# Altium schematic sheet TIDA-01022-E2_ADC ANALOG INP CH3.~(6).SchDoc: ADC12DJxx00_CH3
size 431 x 279 mm; Date: Not shown in title block; ApprovedBy: Not shown in title block; CheckedBy: Not shown in title block; Author: Not shown in title block; CompanyName: Not shown in title block; DrawnBy: Avinash N; Engineer: Not shown in title block; Organization: Not shown in title block; Address1: Not shown in title block; Address2: Not shown in title block; Address3: Not shown in title block; Address4: Not shown in title block; DocumentNumber: 1; Revision: Use project parameter SCH_Rev; SheetNumber: 4; SheetTotal: 26; PageSetup: Record=PageOptions¦CenterHorizontal=True¦CenterVertical=True¦PrintScale=1.00¦XCorrection=1.00¦YCorrection=1.00¦PrintKind=0¦BorderSize=5000000¦LeftOffset=0¦BottomOffset=0¦Orientation=2¦PaperLength=1000¦PaperWidth=1000¦Scale=100¦PaperSource=15¦PrintQuality=600¦MediaType=1¦DitherType=10¦PaperKind=Letter¦PrintScaleMode=1
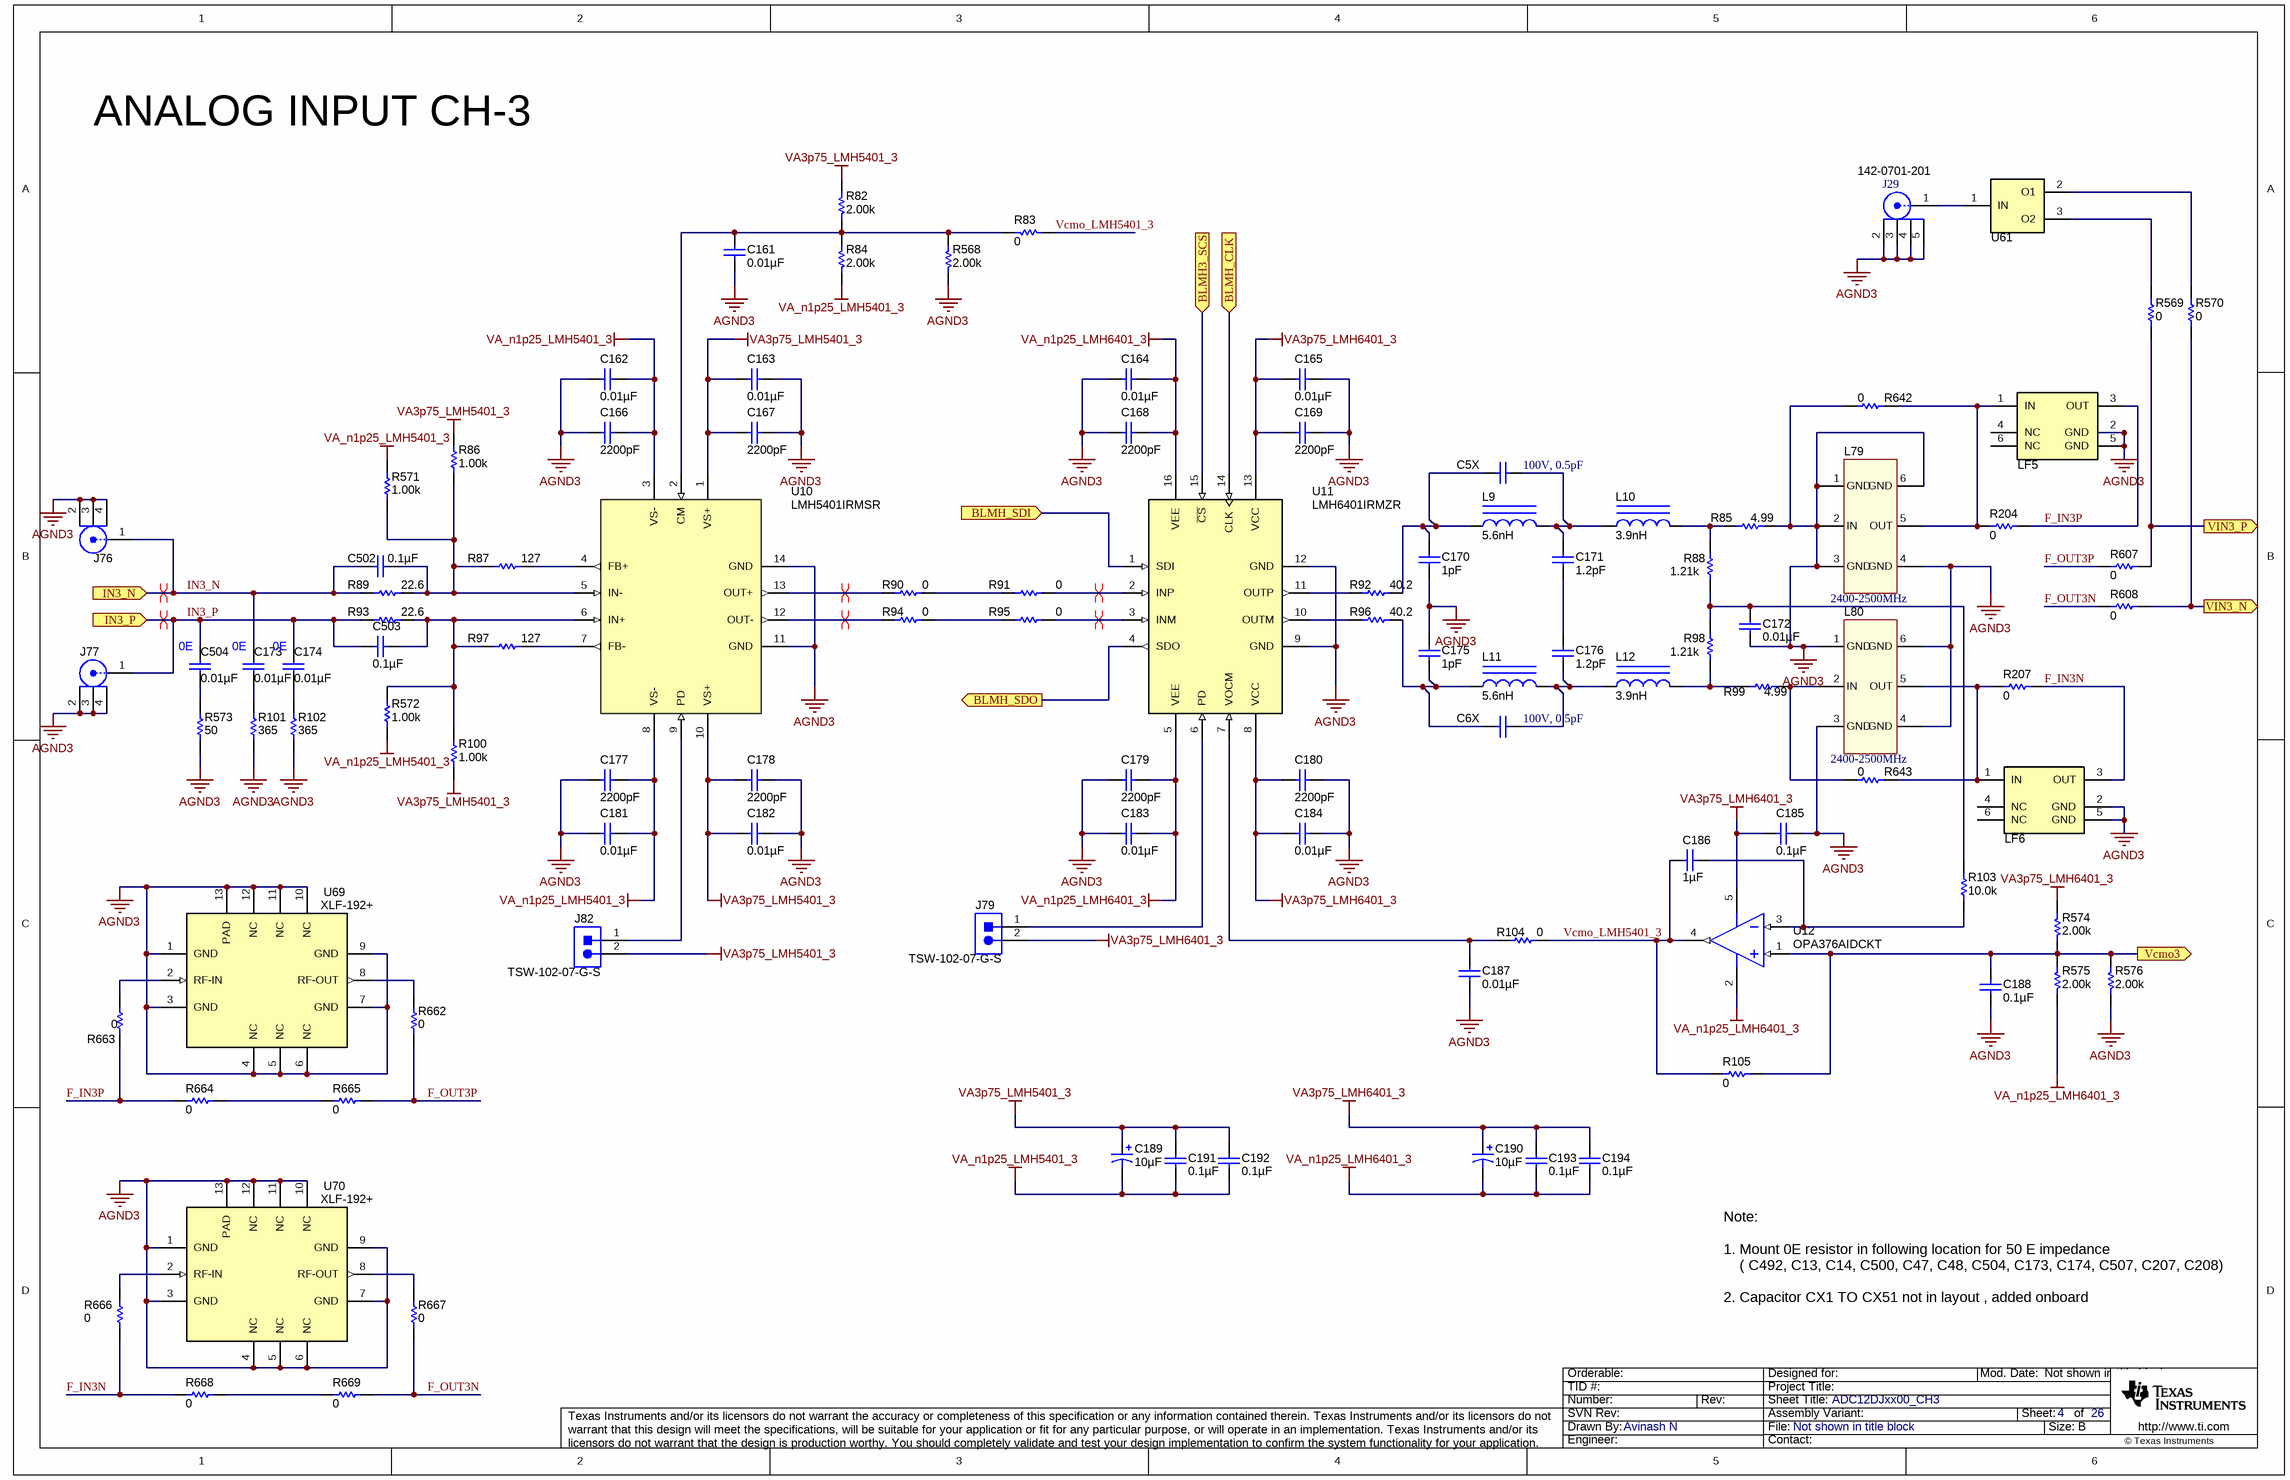
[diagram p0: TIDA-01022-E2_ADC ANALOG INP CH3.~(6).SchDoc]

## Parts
C5X  100V, 0.5pF  [0603_1.6x0.8x0.8mm_Reflow Soldering]
C6X  100V, 0.5pF  [0603_1.6x0.8x0.8mm_Reflow Soldering]
C161  ValueDisplayed: 0.01µF  [0402]  (hidden comment: GRM155R71E103KA01D)
C162  ValueDisplayed: 0.01µF  [0306]  (hidden comment: LLL185R71E103MA01L)
C163  ValueDisplayed: 0.01µF  [0306]  (hidden comment: LLL185R71E103MA01L)
C164  ValueDisplayed: 0.01µF  [0306]  (hidden comment: LLL185R71E103MA01L)
C165  ValueDisplayed: 0.01µF  [0306]  (hidden comment: LLL185R71E103MA01L)
C166  ValueDisplayed: 2200pF  [0306]  (hidden comment: LLL185R71H222MA01L)
C167  ValueDisplayed: 2200pF  [0306]  (hidden comment: LLL185R71H222MA01L)
C168  ValueDisplayed: 2200pF  [0306]  (hidden comment: LLL185R71H222MA01L)
C169  ValueDisplayed: 2200pF  [0306]  (hidden comment: LLL185R71H222MA01L)
C170  ValueDisplayed: 1pF  [0402]  (hidden comment: GRM1555C1H1R0CA01D)
C171  ValueDisplayed: 1.2pF  [0402]  (hidden comment: GRM1555C1H1R2BA01D)
C172  ValueDisplayed: 0.01µF  [0402]  (hidden comment: GRM155R71E103KA01D)
C173  ValueDisplayed: 0.01µF  [0402]  (hidden comment: GRM155R71E103KA01D)
C174  ValueDisplayed: 0.01µF  [0402]  (hidden comment: GRM155R71E103KA01D)
C175  ValueDisplayed: 1pF  [0402]  (hidden comment: GRM1555C1H1R0CA01D)
C176  ValueDisplayed: 1.2pF  [0402]  (hidden comment: GRM1555C1H1R2BA01D)
C177  ValueDisplayed: 2200pF  [0306]  (hidden comment: LLL185R71H222MA01L)
C178  ValueDisplayed: 2200pF  [0306]  (hidden comment: LLL185R71H222MA01L)
C179  ValueDisplayed: 2200pF  [0306]  (hidden comment: LLL185R71H222MA01L)
C180  ValueDisplayed: 2200pF  [0306]  (hidden comment: LLL185R71H222MA01L)
C181  ValueDisplayed: 0.01µF  [0306]  (hidden comment: LLL185R71E103MA01L)
C182  ValueDisplayed: 0.01µF  [0306]  (hidden comment: LLL185R71E103MA01L)
C183  ValueDisplayed: 0.01µF  [0306]  (hidden comment: LLL185R71E103MA01L)
C184  ValueDisplayed: 0.01µF  [0306]  (hidden comment: LLL185R71E103MA01L)
C185  ValueDisplayed: 0.1µF  [0402]  (hidden comment: C1005X5R1A104K050BA)
C186  ValueDisplayed: 1µF  [0603]  (hidden comment: C1608X5R1A105K080AC)
C187  ValueDisplayed: 0.01µF  [0402]  (hidden comment: GRM155R71E103KA01D)
C188  ValueDisplayed: 0.1µF  [0402]  (hidden comment: C1005X5R1A104K050BA)
C189  ValueDisplayed: 10µF  [3216-18]  (hidden comment: TPSA106K010R0900)
C190  ValueDisplayed: 10µF  [3216-18]  (hidden comment: TPSA106K010R0900)
C191  ValueDisplayed: 0.1µF  [0402]  (hidden comment: C1005X5R1A104K050BA)
C192  ValueDisplayed: 0.1µF  [0402]  (hidden comment: C1005X5R1A104K050BA)
C193  ValueDisplayed: 0.1µF  [0402]  (hidden comment: C1005X5R1A104K050BA)
C194  ValueDisplayed: 0.1µF  [0402]  (hidden comment: C1005X5R1A104K050BA)
C502  ValueDisplayed: 0.1µF  [0402]  (hidden comment: GRM155R71C104JA88D)
C503  ValueDisplayed: 0.1µF  [0402]  (hidden comment: GRM155R71C104JA88D)
C504  ValueDisplayed: 0.01µF  [0402]  (hidden comment: GRM155R71E103KA01D)
J29  142-0701-201  [Johnson_142-0701-20x]
J76  142-0771-831  [Johnson_142-0771-831]  (value not drawn)
J77  142-0771-831  [Johnson_142-0771-831]  (value not drawn)
J79  TSW-102-07-G-S  [TSW-102-07-G-S]
J82  TSW-102-07-G-S  [TSW-102-07-G-S]
L9  ValueDisplayed: 5.6nH  [LQW18A]  (hidden comment: LQW18AN5N6D10D)
L10  ValueDisplayed: 3.9nH  [0603HC]  (hidden comment: 0603HC-3N9XJLU)
L11  ValueDisplayed: 5.6nH  [LQW18A]  (hidden comment: LQW18AN5N6D10D)
L12  ValueDisplayed: 3.9nH  [0603HC]  (hidden comment: 0603HC-3N9XJLU)
L79  value 2400-2500MHz  [WE-LPF_0603]  (hidden comment: WE-LPF, 748112024)
L80  value 2400-2500MHz  [WE-LPF_0603]  (hidden comment: WE-LPF, 748112024)
LF5  LFL182G45TC3B746  [FIL_LFL18_TC1]  (value not drawn)
LF6  LFL182G45TC3B746  [FIL_LFL18_TC1]  (value not drawn)
R82  ValueDisplayed: 2.00k  [0402]  (hidden comment: CRCW04022K00FKED)
R83  ValueDisplayed: 0  [0402]  (hidden comment: CRCW04020000Z0ED)
R84  ValueDisplayed: 2.00k  [0402]  (hidden comment: CRCW04022K00FKED)
R85  ValueDisplayed: 4.99  [0402]  (hidden comment: CRCW04024R99FKED)
R86  ValueDisplayed: 1.00k  [0402]  (hidden comment: ERJ-2RKF1001X)
R87  ValueDisplayed: 127  [0402]  (hidden comment: CRCW0402127RFKED)
R88  ValueDisplayed: 1.21k  [0402]  (hidden comment: CRCW04021K21FKED)
R89  ValueDisplayed: 22.6  [0402]  (hidden comment: CRCW040222R6FKED)
R90  ValueDisplayed: 0  [0402]  (hidden comment: CRCW04020000Z0ED)
R91  ValueDisplayed: 0  [0402]  (hidden comment: CRCW04020000Z0ED)
R92  ValueDisplayed: 40.2  [0402]  (hidden comment: CRCW040240R2FKED)
R93  ValueDisplayed: 22.6  [0402]  (hidden comment: CRCW040222R6FKED)
R94  ValueDisplayed: 0  [0402]  (hidden comment: CRCW04020000Z0ED)
R95  ValueDisplayed: 0  [0402]  (hidden comment: CRCW04020000Z0ED)
R96  ValueDisplayed: 40.2  [0402]  (hidden comment: CRCW040240R2FKED)
R97  ValueDisplayed: 127  [0402]  (hidden comment: CRCW0402127RFKED)
R98  ValueDisplayed: 1.21k  [0402]  (hidden comment: CRCW04021K21FKED)
R99  ValueDisplayed: 4.99  [0402]  (hidden comment: CRCW04024R99FKED)
R100  ValueDisplayed: 1.00k  [0402]  (hidden comment: ERJ-2RKF1001X)
R101  ValueDisplayed: 365  [0402]  (hidden comment: CRCW0402365RFKED)
R102  ValueDisplayed: 365  [0402]  (hidden comment: CRCW0402365RFKED)
R103  ValueDisplayed: 10.0k  [0402]  (hidden comment: CRCW040210K0FKED)
R104  ValueDisplayed: 0  [0402]  (hidden comment: CRCW04020000Z0ED)
R105  ValueDisplayed: 0  [0402]  (hidden comment: CRCW04020000Z0ED)
R204  ValueDisplayed: 0  [0402_FILTER]  (hidden comment: CRCW04020000Z0ED)
R207  ValueDisplayed: 0  [0402_FILTER]  (hidden comment: CRCW04020000Z0ED)
R568  ValueDisplayed: 2.00k  [0402]  (hidden comment: CRCW04022K00FKED)
R569  ValueDisplayed: 0  [0201_adc]  (hidden comment: CRCW02010000Z0ED)
R570  ValueDisplayed: 0  [0201_adc]  (hidden comment: CRCW02010000Z0ED)
R571  ValueDisplayed: 1.00k  [0402]  (hidden comment: ERJ-2RKF1001X)
R572  ValueDisplayed: 1.00k  [0402]  (hidden comment: ERJ-2RKF1001X)
R573  ValueDisplayed: 50  [0402]  (hidden comment: FC0402E50R0BTBST1)
R574  ValueDisplayed: 2.00k  [0402]  (hidden comment: CRCW04022K00FKED)
R575  ValueDisplayed: 2.00k  [0402]  (hidden comment: CRCW04022K00FKED)
R576  ValueDisplayed: 2.00k  [0402]  (hidden comment: CRCW04022K00FKED)
R607  ValueDisplayed: 0  [0201_adc]  (hidden comment: CRCW02010000Z0ED)
R608  ValueDisplayed: 0  [0201_adc]  (hidden comment: CRCW02010000Z0ED)
R642  ValueDisplayed: 0  [0402_FILTER]  (hidden comment: CRCW04020000Z0ED)
R643  ValueDisplayed: 0  [0402_FILTER]  (hidden comment: CRCW04020000Z0ED)
R662  ValueDisplayed: 0  [0201_adc]  (hidden comment: CRCW02010000Z0ED)
R663  ValueDisplayed: 0  [0201_adc]  (hidden comment: CRCW02010000Z0ED)
R664  ValueDisplayed: 0  [0201_adc]  (hidden comment: CRCW02010000Z0ED)
R665  ValueDisplayed: 0  [0201_adc]  (hidden comment: CRCW02010000Z0ED)
R666  ValueDisplayed: 0  [0201_adc]  (hidden comment: CRCW02010000Z0ED)
R667  ValueDisplayed: 0  [0201_adc]  (hidden comment: CRCW02010000Z0ED)
R668  ValueDisplayed: 0  [0201_adc]  (hidden comment: CRCW02010000Z0ED)
R669  ValueDisplayed: 0  [0201_adc]  (hidden comment: CRCW02010000Z0ED)
U10  LMH5401IRMSR  [RMS0014A]
U11  LMH6401IRMZR  [RMZ0016A]
U12  OPA376AIDCKT  [DCK0005A_N]
U61  BAL-0006SMG  [Marki_BAL-0006SMG]  (value not drawn)
U69  XLF-192+  [DQ1225]
U70  XLF-192+  [DQ1225]

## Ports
BLMH3_SCS (in), BLMH_CLK (in), BLMH_SDI (in), BLMH_SDO (out), IN3_N (in), IN3_P (in), Vcmo3 (out), VIN3_N (out), VIN3_P (out)

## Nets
AGND3: C161.2 C162.1 C163.1 C164.1 C165.1 C166.2 C167.2 C168.2 C169.2 C170.2 C172.2 C175.2 C177.2 C178.2 C179.2 C180.2 C181.1 C182.1 C183.1 C184.1 C185.1 C187.2 C188.2 J29.2 J29.3 J29.4 J29.5 J76.2 J76.3 J76.4 J77.2 J77.3 J77.4 L79.1(GND) L79.2(IN) L79.3(GND) L79.4(GND) L79.6(GND) L80.1(GND) L80.3(GND) L80.4(GND) L80.6(GND) LF5.2(GND) LF5.5(GND) LF6.2(GND) LF6.5(GND) R85.2 R101.1 R102.1 R568.1 R573.1 R576.1 R642.1 U10.11(GND) U10.14(GND) U11.9(GND) U11.12(GND) U69.1(GND) U69.3(GND) U69.4(NC) U69.5(NC) U69.6(NC) U69.7(GND) U69.9(GND) U69.10(NC) U69.11(NC) U69.12(NC) U69.13(PAD) U70.1(GND) U70.3(GND) U70.4(NC) U70.5(NC) U70.6(NC) U70.7(GND) U70.9(GND) U70.10(NC) U70.11(NC) U70.12(NC) U70.13(PAD)
VA3p75_LMH5401_3: C163.2 C167.1 C178.1 C182.2 C189.1(+) C191.1 C192.1 J82.2 R82.2 R86.2 R100.1 U10.1(VS+) U10.10(VS+)
VA3p75_LMH6401_3: C165.2 C169.1 C180.1 C184.2 C185.2 C190.1(+) C193.1 C194.1 J79.2 R574.2 U11.8(VCC) U11.13(VCC) U12.5(V+)
VA_n1p25_LMH5401_3: C162.2 C166.1 C177.1 C181.2 C189.2(-) C191.2 C192.2 R84.1 R571.2 R572.2 U10.3(VS-) U10.8(VS-)
VA_n1p25_LMH6401_3: C164.2 C168.1 C179.1 C183.2 C190.2(-) C193.2 C194.2 R575.1 U11.5(VEE) U11.16(VEE) U12.2(V-)
BLMH3_SCS: U11.15(~{CS}) ; port BLMH3_SCS
BLMH_CLK: U11.14(CLK) ; port BLMH_CLK
BLMH_SDI: U11.1(SDI) ; port BLMH_SDI
BLMH_SDO: U11.4(SDO) ; port BLMH_SDO
F_IN3N: LF6.3(OUT) R207.2 R666.1 R668.1
F_IN3P: LF5.3(OUT) R204.2 R663.1 R664.1
F_OUT3N: R608.1 R667.1 R669.2
F_OUT3P: R607.1 R662.1 R665.2
IN3_N: C173.1 C502.2 J76.1 R89.1 ; port IN3_N
IN3_P: C174.1 C503.1 C504.1 J77.1 R93.1 ; port IN3_P
Vcmo3: C188.1 R105.1 R574.1 R575.2 R576.2 U12.1(IN+) ; port Vcmo3
Vcmo_LMH5401_3: C186.1 R83.2 R104.1 R105.2 U12.4(OUT)
VIN3_N: R570.2 R608.2 ; port VIN3_N
VIN3_P: R569.2 R607.2 ; port VIN3_P
NetC5X_1: C5X.1 C170.1 L9.1 R92.1
NetC5X_2: C5X.2 C171.1 L9.2 L10.1
NetC6X_1: C6X.1 C175.1 L11.1 R96.1
NetC6X_2: C6X.2 C176.1 L11.2 L12.1
NetC161_1: C161.1 R82.1 R83.1 R84.2 R568.2 U10.2(CM)
NetC171_2: C171.2 C176.2
NetC172_1: C172.1 R88.1 R98.1 R103.2
NetC173_2: C173.2 R101.2
NetC174_2: C174.2 R102.2
NetC186_2: C186.2 R103.1 U12.3(IN-)
NetC187_1: C187.1 R104.2 U11.7(VOCM)
NetC502_1: C502.1 R86.1 R87.1 R89.2 R571.1 U10.5(IN-)
NetC503_2: C503.2 R93.2 R97.1 R100.2 R572.1 U10.6(IN+)
NetC504_2: C504.2 R573.2
NetJ29_1: J29.1 U61.1(IN)
NetJ79_1: J79.1 U11.6(PD)
NetJ82_1: J82.1 U10.9(PD)
NetL10_2: L10.2 R85.1 R88.2
NetL12_2: L12.2 R98.2 R99.1
NetL79_5: L79.5(OUT) LF5.1(IN) R204.1 R642.2
NetL80_2: L80.2(IN) R99.2 R643.1
NetL80_5: L80.5(OUT) LF6.1(IN) R207.1 R643.2
NetR87_2: R87.2 U10.4(FB+)
NetR90_1: R90.1 U10.13(OUT+)
NetR90_2: R90.2 R91.2
NetR91_1: R91.1 U11.2(INP)
NetR92_2: R92.2 U11.11(OUTP)
NetR94_1: R94.1 U10.12(OUT-)
NetR94_2: R94.2 R95.2
NetR95_1: R95.1 U11.3(INM)
NetR96_2: R96.2 U11.10(OUTM)
NetR97_2: R97.2 U10.7(FB-)
NetR569_1: R569.1 U61.3(O2)
NetR570_1: R570.1 U61.2(O1)
NetR662_2: R662.2 U69.8(RF-OUT)
NetR663_2: R663.2 U69.2(RF-IN)
NetR664_2: R664.2 R665.1
NetR666_2: R666.2 U70.2(RF-IN)
NetR667_2: R667.2 U70.8(RF-OUT)
NetR668_2: R668.2 R669.1

Not connected (* = marked no-connect by the designer): LF5 4(NC) 6(NC); LF6 4(NC) 6(NC)

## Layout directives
differential pair: IN3_N, IN3_P, NetR90_1, NetR91_1, NetR94_1, NetR95_1

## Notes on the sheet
- ANALOG INPUT CH-3
- (near C504) 0E
- (near C173) 0E
- (near C174) 0E
- Note:
  1. Mount 0E resistor in following location for 50 E impedance
  ( C492, C13, C14, C500, C47, C48, C504, C173, C174, C507, C207, C208)
  2. Capacitor CX1 TO CX51 not in layout , added onboard

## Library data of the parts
C5X C6X = 885012006086: WCAP-CSGP Ceramic Capacitors, 0603, NP0, 100V, 0.5pF; Rated Voltage: 100V DC
C161 C172-C174 C187 C504 = GRM155R71E103KA01D: CAP, CERM, 0.01 µF, 25 V, +/- 10%, X7R, 0402; Manufacturer: MuRata; Polarized: N; CompType: Capacitor; Value: 0.01uF; U/M: EA; Cap_F: 0.00000001; Tolerance_%: 10; Value1: Unknown; VDC_V: 25; Value2: 25V; TaMin_C: -55; TaMax_C: 125; SizeArea_mm2: 0.5; SizeAreaWB_mm2: 3; SizeX_mm: 1; SizeZ_mm: 0.6; AEC Category: Q200
C162-C165 C181-C184 = LLL185R71E103MA01L: CAP, CERM, 0.01 µF, 25 V, +/- 20%, X7R, 0306; Manufacturer: MuRata; Polarized: N; CompType: Capacitor; Value: 0.01uF; U/M: EA; Cap_F: 0.00000001; Tolerance_%: 20; Value1: Unknown; VDC_V: 25; Value2: 25V; TaMin_C: -55; TaMax_C: 125; SizeArea_mm2: 1.28; SizeAreaWB_mm2: 4.68; SizeX_mm: 0.8; SizeY_mm: 1.6; SizeZ_mm: 0.6; AEC Category: Q200
C166-C169 C177-C180 = LLL185R71H222MA01L: CAP, CERM, 2200 pF, 50 V, +/- 20%, X7R, 0306; Manufacturer: MuRata; Polarized: N; CompType: Capacitor; Value: 2200pF; U/M: EA; Cap_F: 0.0000000022; Tolerance_%: 20; Value1: Unknown; VDC_V: 50; Value2: 50V; TaMin_C: -55; TaMax_C: 125; SizeArea_mm2: 1.28; SizeAreaWB_mm2: 4.68; SizeX_mm: 0.8; SizeY_mm: 1.6; SizeZ_mm: 0.6; AEC Category: Q200
C170 C175 = GRM1555C1H1R0CA01D: CAP, CERM, 1 pF, 50 V, +/- 5%, C0G/NP0, 0402; Manufacturer: MuRata; Polarized: N; CompType: Capacitor; Value: 1pF; U/M: EA; Cap_F: 0.000000000001; Tolerance_%: 5; Value1: Unknown; VDC_V: 50; Value2: 50V; TaMin_C: -55; TaMax_C: 125; SizeArea_mm2: 0.5; SizeAreaWB_mm2: 3; SizeX_mm: 1; SizeZ_mm: 0.6; AEC Category: Q200
C171 C176 = GRM1555C1H1R2BA01D: CAP, CERM, 1.2 pF, 50 V, +/- 8.3%, C0G/NP0, 0402; Manufacturer: MuRata; Polarized: N; CompType: Capacitor; Value: 1.2pF; U/M: EA; Cap_F: 0.0000000000012; Tolerance_%: 8.3; Value1: Unknown; VDC_V: 50; Value2: 50V; TaMin_C: -55; TaMax_C: 125; SizeArea_mm2: 0.5; SizeAreaWB_mm2: 3; SizeX_mm: 1; SizeZ_mm: 0.6; AEC Category: Q200
C185 C188 C191-C194 = C1005X5R1A104K050BA: CAP, CERM, 0.1 µF, 10 V, +/- 10%, X5R, 0402; Manufacturer: TDK; Polarized: N; CompType: Capacitor; Value: 0.1uF; U/M: EA; Cap_F: 0.0000001; Tolerance_%: 10; Value1: Unknown; Value2: 10V; TaMin_C: -55; TaMax_C: 85; SizeArea_mm2: 0.5; SizeAreaWB_mm2: 3; SizeX_mm: 1; SizeZ_mm: 0.6; AEC Category: Q200
C186 = C1608X5R1A105K080AC: CAP, CERM, 1 µF, 10 V, +/- 10%, X5R, 0603; Manufacturer: TDK; Polarized: N; CompType: Capacitor; Value: 1uF; U/M: EA; Cap_F: 0.000001; Tolerance_%: 10; Value1: Unknown; Value2: 10V; TaMin_C: -55; TaMax_C: 85; SizeArea_mm2: 1.28; SizeAreaWB_mm2: 4.68; SizeX_mm: 1.6; SizeY_mm: 0.8; SizeZ_mm: 1; AEC Category: Q200
C189 C190 = TPSA106K010R0900: CAP, TA, 10 µF, 10 V, +/- 10%, 0.9 ohm, SMD; Manufacturer: AVX; Polarized: Y; CompType: Capacitor; Value: 10uF; U/M: EA; Cap_F: 0.00001; Tolerance_%: 10; Value1: 0.9 ohm; Value2: 10V; ESR_ohm: 0.9; IRMS_A: 0.26; TaMin_C: -55; TaMax_C: 125; Cap_Case: A; SizeAreaWB_mm2: 10.92; SizeArea_mm2: 5.12; SizeX_mm: 3.2; SizeY_mm: 1.6; SizeZ_mm: 1.8; AEC Category: Q200
C502 C503 = GRM155R71C104JA88D: CAP, CERM, 0.1 µF, 16 V, +/- 5%, X7R, 0402; Manufacturer: MuRata; Polarized: N; CompType: Capacitor; Value: 0.1uF; U/M: EA; Cap_F: 0.0000001; Tolerance_%: 5; Value1: Unknown; VDC_V: 16; Value2: 16V; TaMin_C: -55; TaMax_C: 125; SizeArea_mm2: 0.5; SizeAreaWB_mm2: 3; SizeX_mm: 1; SizeZ_mm: 0.6; AEC Category: Q200
J29 = 142-0701-201: Connector, TH, SMA; Manufacturer: Emerson Network Power; SymbolCreator: X0208326
J76 J77 = 142-0771-831: JACK, SMA, 50 Ohm, Gold, Edge Mount; Manufacturer: Johnson; SymbolCreator: Altium; Gender: Female; Voltage_V: 170
J79 J82 = TSW-102-07-G-S: Header, 100mil, 2x1, Gold, TH; Manufacturer: Samtec; SymbolCreator: a0412235; Pitch_mm: 2.54; Gender: Male; Shrouded: N; Row_Count: 1; Current_A: 6.3; Voltage_V: 550; Cert_CSA: Y
L9 L11 = LQW18AN5N6D10D: Inductor, Wirewound, 5.6 nH, 0.9 A, 0.045 ohm, SMD; Manufacturer: MuRata; Value: 5.6nH; Ind_H: 5.6E-9; Imax_A: 0.9; Irms: 0.9A @ C rise; DCR_ohm: 0.045; Value2: 0.9A; SizeAreaWB_mm2: 4.68; SizeArea_mm2: 1.28; SizeX_mm: 1.6; SizeY_mm: 0.8; SizeZ_mm: 1; AEC Category: Q200; AEC Qualified: N
L10 L12 = 0603HC-3N9XJLU: Inductor, Wirewound, Ceramic, 3.9 nH, 2.2 A, 0.054 ohm, SMD; Manufacturer: Coilcraft; Value: 3.9nH; Ind_H: 3.9E-9; Imax_A: 2.2; Irms: 2.4A @ 20C rise; DCR_ohm: 0.054; Value2: 2.2A; SizeAreaWB_mm2: 5.936; SizeArea_mm2: 2.016; SizeX_mm: 1.8; SizeY_mm: 1.12; SizeZ_mm: 1.02; AEC Category: Q200
L79 L80 = WE-LPF, 748112024: WE-LPF Multilayer Chip Low-Pass Filter, size 0603, 2400-2500MHz
LF5 LF6 = LFL182G45TC3B746: Filter for Communication Equipment, SMD; Manufacturer: MuRata; SymbolCreator: Altium; SizeAreaWB_mm2: 4.68; SizeArea_mm2: 1.28; SizeX_mm: 1.6; SizeY_mm: 0.8; SizeZ_mm: 0.7
R82 R84 R568 R574-R576 = CRCW04022K00FKED: RES, 2.00 k, 1%, 0.063 W, 0402; Manufacturer: Vishay-Dale; CompType: Resistor; Value: 2.00k; Res_ohm: 2000; Value_Code: 2k00; Tolerance_%: 1; Power_W: 0.063; Value2: 0.063W; VDC_V: 50; TempCo: 100 ppm/C; SizeArea_mm2: 0.5; SizeZ_mm: 0.6; EIA_Code: E96; U/M: EA; AEC Category: Q200
R83 R90 R91 R94 R95 R104 R105 R204 R207 R642 R643 = CRCW04020000Z0ED: RES, 0, 5%, 0.063 W, 0402; Manufacturer: Vishay-Dale; CompType: Resistor; Value: 0; Value_Code: 0000; Tolerance_%: 5; Power_W: 0.063; Value2: 0.063W; VDC_V: 50; TempCo: 200 ppm/C; SizeArea_mm2: 0.5; SizeX_mm: 1; SizeZ_mm: 0.6; EIA_Code: E24; U/M: EA; AEC Category: Q200
R85 R99 = CRCW04024R99FKED: RES, 4.99, 1%, 0.063 W, 0402; Manufacturer: Vishay-Dale; CompType: Resistor; Value: 4.99; Value_Code: 4R99; Tolerance_%: 1; Power_W: 0.063; Value2: 0.063W; VDC_V: 50; TempCo: 100 ppm/C; SizeArea_mm2: 0.5; SizeZ_mm: 0.6; EIA_Code: E96; U/M: EA; AEC Category: Q200
R86 R100 R571 R572 = ERJ-2RKF1001X: RES, 1.00 k, 1%, 0.1 W, 0402; Manufacturer: Panasonic; CompType: Resistor; Value: 1.00k; Res_ohm: 1000; Value_Code: 1k00; Tolerance_%: 1; Power_W: 0.1; Value2: 0.1W; VDC_V: 50; TempCo: 100 ppm/C; SizeArea_mm2: 0.5; SizeZ_mm: 0.6; EIA_Code: E96; U/M: EA; AEC Category: Q200
R87 R97 = CRCW0402127RFKED: RES, 127, 1%, 0.063 W, 0402; Manufacturer: Vishay-Dale; CompType: Resistor; Value: 127; Value_Code: 127R; Tolerance_%: 1; Power_W: 0.063; Value2: 0.063W; VDC_V: 50; TempCo: 100 ppm/C; SizeArea_mm2: 0.5; SizeZ_mm: 0.6; EIA_Code: E96; U/M: EA; AEC Category: Q200
R88 R98 = CRCW04021K21FKED: RES, 1.21 k, 1%, 0.063 W, 0402; Manufacturer: Vishay-Dale; CompType: Resistor; Value: 1.21k; Res_ohm: 1210; Value_Code: 1k21; Tolerance_%: 1; Power_W: 0.063; Value2: 0.063W; VDC_V: 50; TempCo: 100 ppm/C; SizeArea_mm2: 0.5; SizeZ_mm: 0.6; EIA_Code: E96; U/M: EA; AEC Category: Q200
R89 R93 = CRCW040222R6FKED: RES, 22.6, 1%, 0.063 W, 0402; Manufacturer: Vishay-Dale; CompType: Resistor; Value: 22.6; Value_Code: 22R6; Tolerance_%: 1; Power_W: 0.063; Value2: 0.063W; VDC_V: 50; TempCo: 100 ppm/C; SizeArea_mm2: 0.5; SizeZ_mm: 0.6; EIA_Code: E96; U/M: EA; AEC Category: Q200
R92 R96 = CRCW040240R2FKED: RES, 40.2, 1%, 0.063 W, 0402; Manufacturer: Vishay-Dale; CompType: Resistor; Value: 40.2; Value_Code: 40R2; Tolerance_%: 1; Power_W: 0.063; Value2: 0.063W; VDC_V: 50; TempCo: 100 ppm/C; SizeArea_mm2: 0.5; SizeZ_mm: 0.6; EIA_Code: E96; U/M: EA; AEC Category: Q200
R101 R102 = CRCW0402365RFKED: RES, 365, 1%, 0.063 W, 0402; Manufacturer: Vishay-Dale; CompType: Resistor; Value: 365; Value_Code: 365R; Tolerance_%: 1; Power_W: 0.063; Value2: 0.063W; VDC_V: 50; TempCo: 100 ppm/C; SizeArea_mm2: 0.5; SizeZ_mm: 0.6; EIA_Code: E96; U/M: EA; AEC Category: Q200
R103 = CRCW040210K0FKED: RES, 10.0 k, 1%, 0.063 W, 0402; Manufacturer: Vishay-Dale; CompType: Resistor; Value: 10.0k; Res_ohm: 10000; Value_Code: 10k0; Tolerance_%: 1; Power_W: 0.063; Value2: 0.063W; VDC_V: 50; TempCo: 100 ppm/C; SizeArea_mm2: 0.5; SizeZ_mm: 0.6; EIA_Code: E96; U/M: EA; AEC Category: Q200
R569 R570 R607 R608 R662-R669 = CRCW02010000Z0ED: RES, 0, 5%, 0.05 W, 0201; Manufacturer: Vishay-Dale; CompType: Resistor; Value: 0; Value_Code: 0000; Tolerance_%: 5; Power_W: 0.05; Value2: 0.05W; TempCo: ppm/C; SizeArea_mm2: 0.18; SizeX_mm: 0.6; SizeY_mm: 0.3; SizeZ_mm: 0.26; EIA_Code: E24; U/M: EA; AEC Category: Q200; AEC Qualified: N
R573 = FC0402E50R0BTBST1: RES, 50, 0.1%, 0.5 W, 0402; Manufacturer: Vishay Thin Film; CompType: Resistor; Value: 50; Value_Code: 50R0; Tolerance_%: 0.1; Power_W: 0.5; Value2: 0.5W; TempCo: 0.1 ppm/C; SizeX_mm: 1; SizeZ_mm: 0.6; U/M: EA; AEC Category: Q200; AEC Qualified: N
U10 = LMH5401IRMSR: 8GHz Ultra Wideband Fully Differential Amplifier, RMS0014A (UQFN-14); Alternate PartNumber: LMH5401IRMST; Manufacturer: Texas Instruments; SymbolCreator: Altium; SizeArea_mm2: 6.25; SizeAreaWB_mm2: 12.25; SizeX_mm: 2.5; SizeZ_mm: 0.6; CompType: IC; U/M: EA
U11 = LMH6401IRMZR: 4.5 GHz Ultra Wideband Digital Variable Gain Amplifier, RMZ0016A (UQFN-HR-16); Alternate PartNumber: LMH6401IRMZT; Manufacturer: Texas Instruments; SymbolCreator: Altium; SizeArea_mm2: 9; SizeAreaWB_mm2: 16; SizeX_mm: 3; SizeZ_mm: 0.65; CompType: IC; U/M: EA
U12 = OPA376AIDCKT: Precision, Low Noise, Low Iq Operational Amplifier, 2.2 to 5.5 V, -40 to 125 degC, 5-pin SOT23 (DCK0005A), Green (RoHS & no Sb/Br); Manufacturer: Texas Instruments; Alternate PartNumber: Equivalent; CMRR(Min)(dB): 76; IIB(Max)(pA): 10; Iq per channel(Max)(mA): 0.95; Number of Channels: 1; Offset Drift(Typ)(uV/C): 0.32; Slew Rate(Typ)(V/us): 2; Sub Family: Low Input Bias Current Amp (<=10pA), Low Noise Amp (<=10nV/rtHz), Low Offset Voltage Amplifier (<=500uV), Low Supply Voltage Amplifier (<=2.7V), Precision Amplifier; Total Supply Voltage(Max)(+5V is 5, +/-5V is 10): 5.5; Total Supply Voltage(Min)(+5V is 5, +/-5V is 10): 2.2; Vio (25C)(Max)(mV): 0.025; Vn at 1kHz(Typ)(nV/rtHz): 7.5
U61 = BAL-0006SMG: Broadband Balun, 500 kHz to 6 GHz; Manufacturer: Marki Microwave; SymbolCreator: Altium; SizeAreaWB_mm2: 102.6169; SizeArea_mm2: 66.0969; SizeX_mm: 8.13; SizeZ_mm: 3.94
U69 U70 = CMP-0077784-1: Reflectionless Low Pass Filter, SMD; Manufacturer: Minicircuits; SizeArea_mm2: 9; SizeAreaWB_mm2: 16; SizeY_mm: 3; SizeZ_mm: 0.89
